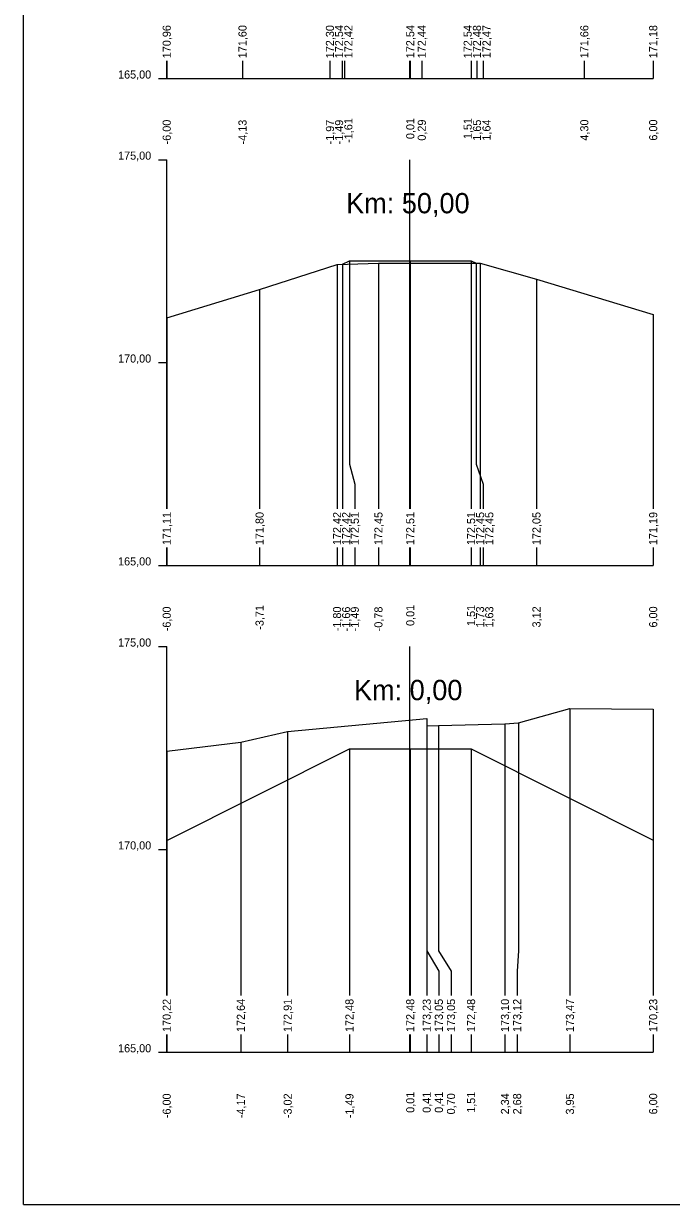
# Model space of a CAD drawing. Extents: x -614174 to -599765, y -1185887 to -1181080.
# Drawn here: x -601084.96 to -601068.98, y -1184449.09 to -1184419.99 of the extents above; entities that cross this region are included whole.
import ezdxf

# ---------------------------------------------------------------- set-up
doc = ezdxf.new("R2010")
doc.units = 0
for name, color, linetype in [('11', 7, 'Continuous'), ('16', 7, 'Continuous'), ('21', 7, 'Continuous'), ('28', 7, 'Continuous'), ('59', 7, 'Continuous'), ('8', 7, 'Continuous'), ('návrh', 7, 'Continuous')]:
    doc.layers.add(name, color=color, linetype=linetype)

msp = doc.modelspace()

# ---------------------------------------------------------------- linework, layer by layer
for points in [[(-601077.088, -1184425.918), (-601076.919, -1184425.834), (-601075.419, -1184425.834), (-601073.919, -1184425.834), (-601073.796, -1184425.895)], [(-601076.919, -1184425.834), (-601076.919, -1184425.834), (-601076.919, -1184425.834)], [(-601075.419, -1184425.834), (-601075.419, -1184425.834), (-601075.419, -1184425.834)], [(-601073.919, -1184425.834), (-601073.919, -1184425.834), (-601073.919, -1184425.834)], [(-601081.427, -1184427.237), (-601079.136, -1184426.541), (-601077.225, -1184425.922), (-601076.204, -1184425.895), (-601073.696, -1184425.895), (-601072.306, -1184426.289), (-601069.427, -1184427.154)], [(-601077.088, -1184425.918), (-601077.088, -1184425.918), (-601077.088, -1184425.918)], [(-601081.427, -1184437.917), (-601079.598, -1184437.7), (-601078.443, -1184437.432), (-601075.014, -1184437.116), (-601075.013, -1184437.295), (-601074.725, -1184437.29), (-601073.083, -1184437.247), (-601072.748, -1184437.218), (-601071.481, -1184436.87), (-601069.427, -1184436.884)], [(-601081.427, -1184440.12), (-601076.919, -1184437.866), (-601075.419, -1184437.866), (-601073.919, -1184437.866), (-601069.427, -1184440.112)], [(-601076.919, -1184437.866), (-601076.919, -1184437.866)], [(-601075.419, -1184437.866), (-601075.419, -1184437.866)], [(-601073.919, -1184437.866), (-601073.919, -1184437.866)]]:
    msp.add_lwpolyline(points)
at = {"layer": '11'}
for points in [[(-601081.427, -1184420.902), (-601081.427, -1184421.342)], [(-601079.557, -1184420.902), (-601079.557, -1184421.342)], [(-601077.4, -1184420.902), (-601077.4, -1184421.342)], [(-601077.1, -1184420.902), (-601077.1, -1184421.342)], [(-601077.039, -1184420.902), (-601077.039, -1184421.342)], [(-601075.419, -1184420.902), (-601075.419, -1184421.342)], [(-601075.135, -1184420.902), (-601075.135, -1184421.342)], [(-601073.919, -1184420.902), (-601073.919, -1184421.342)], [(-601073.774, -1184420.902), (-601073.774, -1184421.342)], [(-601073.619, -1184420.902), (-601073.619, -1184421.342)], [(-601071.126, -1184420.902), (-601071.126, -1184421.342)], [(-601069.427, -1184420.902), (-601069.427, -1184421.342)], [(-601076.919, -1184425.834), (-601076.919, -1184430.842), (-601076.788, -1184431.342), (-601076.788, -1184431.944)], [(-601075.419, -1184425.834), (-601075.419, -1184430.842), (-601075.419, -1184431.342), (-601075.419, -1184431.944)], [(-601073.919, -1184425.834), (-601073.919, -1184430.842), (-601073.919, -1184431.342), (-601073.919, -1184431.944)], [(-601077.225, -1184425.922), (-601077.225, -1184430.842), (-601077.225, -1184431.342), (-601077.225, -1184431.944)], [(-601077.088, -1184425.918), (-601077.088, -1184430.842), (-601077.088, -1184431.342), (-601077.088, -1184431.944)], [(-601076.204, -1184425.895), (-601076.204, -1184430.842), (-601076.204, -1184431.342), (-601076.204, -1184431.944)], [(-601073.796, -1184425.895), (-601073.796, -1184430.842), (-601073.619, -1184431.342), (-601073.619, -1184431.944)], [(-601073.696, -1184425.895), (-601073.696, -1184430.842), (-601073.696, -1184431.342), (-601073.696, -1184431.944)], [(-601072.306, -1184426.289), (-601072.306, -1184430.842), (-601072.306, -1184431.342), (-601072.306, -1184431.944)], [(-601079.136, -1184426.541), (-601079.136, -1184430.842), (-601079.136, -1184431.342), (-601079.136, -1184431.944)], [(-601081.427, -1184427.237), (-601081.427, -1184430.842), (-601081.427, -1184431.342), (-601081.427, -1184431.944)], [(-601069.427, -1184427.154), (-601069.427, -1184430.842), (-601069.427, -1184431.342), (-601069.427, -1184431.944)], [(-601081.427, -1184432.902), (-601081.427, -1184433.342)], [(-601079.136, -1184432.902), (-601079.136, -1184433.342)], [(-601077.225, -1184432.902), (-601077.225, -1184433.342)], [(-601077.088, -1184432.902), (-601077.088, -1184433.342)], [(-601076.788, -1184432.902), (-601076.788, -1184433.342)], [(-601076.204, -1184432.902), (-601076.204, -1184433.342)], [(-601075.419, -1184432.902), (-601075.419, -1184433.342)], [(-601073.919, -1184432.902), (-601073.919, -1184433.342)], [(-601073.696, -1184432.902), (-601073.696, -1184433.342)], [(-601073.619, -1184432.902), (-601073.619, -1184433.342)], [(-601072.306, -1184432.902), (-601072.306, -1184433.342)], [(-601069.427, -1184432.902), (-601069.427, -1184433.342)], [(-601071.481, -1184436.87), (-601071.481, -1184442.842), (-601071.481, -1184443.342), (-601071.481, -1184443.944)], [(-601069.427, -1184436.884), (-601069.427, -1184442.842), (-601069.427, -1184443.342), (-601069.427, -1184443.944)], [(-601075.014, -1184437.116), (-601075.014, -1184442.842), (-601075.014, -1184443.342), (-601075.014, -1184443.944)], [(-601078.443, -1184437.432), (-601078.443, -1184442.842), (-601078.443, -1184443.342), (-601078.443, -1184443.944)], [(-601075.013, -1184437.295), (-601075.013, -1184442.842), (-601074.714, -1184443.342), (-601074.714, -1184443.944)], [(-601074.725, -1184437.29), (-601074.725, -1184442.842), (-601074.414, -1184443.342), (-601074.414, -1184443.944)], [(-601073.083, -1184437.247), (-601073.083, -1184442.842), (-601073.083, -1184443.342), (-601073.083, -1184443.944)], [(-601072.748, -1184437.218), (-601072.748, -1184442.842), (-601072.783, -1184443.342), (-601072.783, -1184443.944)], [(-601079.598, -1184437.7), (-601079.598, -1184442.842), (-601079.598, -1184443.342), (-601079.598, -1184443.944)], [(-601081.427, -1184437.917), (-601081.427, -1184442.842), (-601081.427, -1184443.342), (-601081.427, -1184443.944)], [(-601076.919, -1184437.866), (-601076.919, -1184442.842), (-601076.919, -1184443.342), (-601076.919, -1184443.944)], [(-601075.419, -1184437.866), (-601075.419, -1184442.842), (-601075.419, -1184443.342), (-601075.419, -1184443.944)], [(-601073.919, -1184437.866), (-601073.919, -1184442.842), (-601073.919, -1184443.342), (-601073.919, -1184443.944)], [(-601081.427, -1184440.12), (-601081.427, -1184442.842), (-601081.427, -1184443.342), (-601081.427, -1184443.944)], [(-601069.427, -1184440.112), (-601069.427, -1184442.842), (-601069.427, -1184443.342), (-601069.427, -1184443.944)], [(-601081.427, -1184444.902), (-601081.427, -1184445.342)], [(-601081.427, -1184444.902), (-601081.427, -1184445.342)], [(-601079.598, -1184444.902), (-601079.598, -1184445.342)], [(-601078.443, -1184444.902), (-601078.443, -1184445.342)], [(-601076.919, -1184444.902), (-601076.919, -1184445.342)], [(-601075.419, -1184444.902), (-601075.419, -1184445.342)], [(-601075.014, -1184444.902), (-601075.014, -1184445.342)], [(-601074.714, -1184444.902), (-601074.714, -1184445.342)], [(-601074.414, -1184444.902), (-601074.414, -1184445.342)], [(-601073.919, -1184444.902), (-601073.919, -1184445.342)], [(-601073.083, -1184444.902), (-601073.083, -1184445.342)], [(-601072.783, -1184444.902), (-601072.783, -1184445.342)], [(-601071.481, -1184444.902), (-601071.481, -1184445.342)], [(-601069.427, -1184444.902), (-601069.427, -1184445.342)], [(-601069.427, -1184444.902), (-601069.427, -1184445.342)]]:
    msp.add_lwpolyline(points, dxfattribs=at)
at = {"layer": '16'}
for p, q in [((-601081.427, -1184421.342), (-601069.427, -1184421.342)), ((-601081.427, -1184433.342), (-601069.427, -1184433.342)), ((-601081.427, -1184445.342), (-601069.427, -1184445.342))]:
    msp.add_line(p, q, dxfattribs=at)
msp.add_lwpolyline([(-601073.796, -1184425.895), (-601073.796, -1184425.895), (-601073.796, -1184425.895)], dxfattribs=at)
at = {"layer": '21'}
for p, q in [((-601081.627, -1184421.342), (-601081.427, -1184421.342)), ((-601081.627, -1184423.342), (-601081.427, -1184423.342)), ((-601081.627, -1184428.342), (-601081.427, -1184428.342)), ((-601081.627, -1184433.342), (-601081.427, -1184433.342)), ((-601081.627, -1184435.342), (-601081.427, -1184435.342)), ((-601081.627, -1184440.342), (-601081.427, -1184440.342)), ((-601081.627, -1184445.342), (-601081.427, -1184445.342))]:
    msp.add_line(p, q, dxfattribs=at)
at = {"layer": '28'}
for p, q in [((-601075.427, -1184421.342), (-601075.427, -1184420.902)), ((-601075.427, -1184431.944), (-601075.427, -1184423.342)), ((-601075.427, -1184433.342), (-601075.427, -1184432.902)), ((-601075.427, -1184443.944), (-601075.427, -1184435.342)), ((-601075.427, -1184445.342), (-601075.427, -1184444.902))]:
    msp.add_line(p, q, dxfattribs=at)
at = {"layer": '8'}
for p, q in [((-601081.427, -1184421.342), (-601081.427, -1184420.902)), ((-601081.427, -1184431.944), (-601081.427, -1184423.342)), ((-601081.427, -1184433.342), (-601081.427, -1184432.902)), ((-601081.427, -1184443.944), (-601081.427, -1184435.342)), ((-601081.427, -1184445.342), (-601081.427, -1184444.902))]:
    msp.add_line(p, q, dxfattribs=at)
at = {"layer": 'návrh'}
for q in [(-601084.957, -1184419.39), (-601063.957, -1184449.09)]:
    msp.add_line((-601084.957, -1184449.09), q, dxfattribs=at)

# ---------------------------------------------------------------- texts
at = {"layer": '16'}
for s, p in [('170,96', (-601081.327, -1184420.842)), ('171,60', (-601079.457, -1184420.842)), ('172,30', (-601077.3, -1184420.842)), ('172,54', (-601077.076, -1184420.842)), ('172,42', (-601076.846, -1184420.842)), ('172,54', (-601075.319, -1184420.842)), ('172,44', (-601075.035, -1184420.842)), ('172,54', (-601073.903, -1184420.842)), ('172,48', (-601073.674, -1184420.842)), ('172,47', (-601073.439, -1184420.842)), ('171,66', (-601071.026, -1184420.842)), ('171,18', (-601069.327, -1184420.842)), ('171,11', (-601081.327, -1184432.842)), ('171,80', (-601079.036, -1184432.842)), ('172,42', (-601077.125, -1184432.842)), ('172,42', (-601076.901, -1184432.842)), ('172,51', (-601076.688, -1184432.842)), ('172,45', (-601076.104, -1184432.842)), ('172,51', (-601075.319, -1184432.842)), ('172,51', (-601073.819, -1184432.842)), ('172,45', (-601073.596, -1184432.842)), ('172,45', (-601073.37, -1184432.842)), ('172,05', (-601072.206, -1184432.842)), ('171,19', (-601069.327, -1184432.842)), ('170,22', (-601081.327, -1184444.842)), ('172,64', (-601079.498, -1184444.842)), ('172,91', (-601078.343, -1184444.842)), ('172,48', (-601076.819, -1184444.842)), ('172,48', (-601075.319, -1184444.842)), ('173,23', (-601074.914, -1184444.842)), ('173,05', (-601074.614, -1184444.842)), ('173,05', (-601074.314, -1184444.842)), ('172,48', (-601073.819, -1184444.842)), ('173,10', (-601072.983, -1184444.842)), ('173,12', (-601072.683, -1184444.842)), ('173,47', (-601071.381, -1184444.842)), ('170,23', (-601069.327, -1184444.842))]:
    msp.add_text(s, height=0.2, rotation=90, dxfattribs=at).set_placement(p)
at = {"layer": '21'}
for s, p in [('165,00', (-601082.627, -1184421.342)), ('175,00', (-601082.627, -1184423.342)), ('170,00', (-601082.627, -1184428.342)), ('165,00', (-601082.627, -1184433.342)), ('175,00', (-601082.627, -1184435.342)), ('170,00', (-601082.627, -1184440.342)), ('165,00', (-601082.627, -1184445.342))]:
    msp.add_text(s, height=0.2, dxfattribs=at).set_placement(p)
at = {"layer": '28'}
for s, p in [('Km: 50,00', (-601077.002, -1184424.663)), ('Km: 0,00', (-601076.808, -1184436.663))]:
    msp.add_text(s, height=0.5, dxfattribs=at).set_placement(p)
at = {"layer": '59'}
for s, p in [('-1,61', (-601076.846, -1184422.927)), ('0,01', (-601075.319, -1184422.834)), ('1,51', (-601073.903, -1184422.834)), ('-6,00', (-601081.327, -1184422.965)), ('-4,13', (-601079.457, -1184422.966)), ('-1,97', (-601077.3, -1184422.966)), ('-1,49', (-601077.076, -1184422.966)), ('0,29', (-601075.035, -1184422.873)), ('1,65', (-601073.674, -1184422.875)), ('1,64', (-601073.439, -1184422.872)), ('4,30', (-601071.026, -1184422.872)), ('6,00', (-601069.327, -1184422.872)), ('-6,00', (-601081.327, -1184434.965)), ('-3,71', (-601079.036, -1184434.927)), ('-1,80', (-601077.125, -1184434.965)), ('-1,66', (-601076.901, -1184434.966)), ('-1,49', (-601076.688, -1184434.966)), ('-0,78', (-601076.104, -1184434.966)), ('0,01', (-601075.319, -1184434.834)), ('1,51', (-601073.819, -1184434.834)), ('1,73', (-601073.596, -1184434.873)), ('1,63', (-601073.37, -1184434.873)), ('3,12', (-601072.206, -1184434.871)), ('6,00', (-601069.327, -1184434.872)), ('-6,00', (-601081.327, -1184446.965)), ('-6,00', (-601081.327, -1184446.965)), ('-4,17', (-601079.498, -1184446.966)), ('-3,02', (-601078.343, -1184446.964)), ('-1,49', (-601076.819, -1184446.966)), ('0,01', (-601075.319, -1184446.834)), ('0,41', (-601074.914, -1184446.834)), ('0,41', (-601074.614, -1184446.834)), ('0,70', (-601074.314, -1184446.872)), ('1,51', (-601073.819, -1184446.834)), ('2,34', (-601072.983, -1184446.872)), ('2,68', (-601072.683, -1184446.873)), ('3,95', (-601071.381, -1184446.875)), ('6,00', (-601069.327, -1184446.872)), ('6,00', (-601069.327, -1184446.872))]:
    msp.add_text(s, height=0.2, rotation=90, dxfattribs=at).set_placement(p)

doc.saveas('drawing.dxf')
